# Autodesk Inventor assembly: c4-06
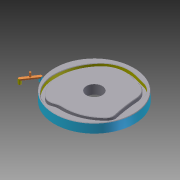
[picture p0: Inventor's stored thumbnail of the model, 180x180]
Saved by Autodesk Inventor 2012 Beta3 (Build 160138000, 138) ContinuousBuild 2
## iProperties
Created: 2010-11
Part Number: c4-06
Document SubType Name: Assembly
Designer: Beta-8540w
Author: Beta-8540w
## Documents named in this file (3)
- C:\Inventor 2012 Essentials\Assemblies\Chapter 4\c4-06.iam
- C:\Inventor 2012 Essentials\Parts\Chapter 4\c4-05.ipt
- C:\Inventor 2012 Essentials\Parts\Chapter 4\c4-06.ipt
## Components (2 placed, 2 different names)
1. c4-05:1 — Mate:1, Tangent:1
2. c4-06:1 — Mate:1, Tangent:1
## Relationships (2: Mate 1, Tangent 1)
- Mate:1: c4-05:1 ↔ c4-06:1
- Tangent:1: c4-05:1 ↔ c4-06:1
